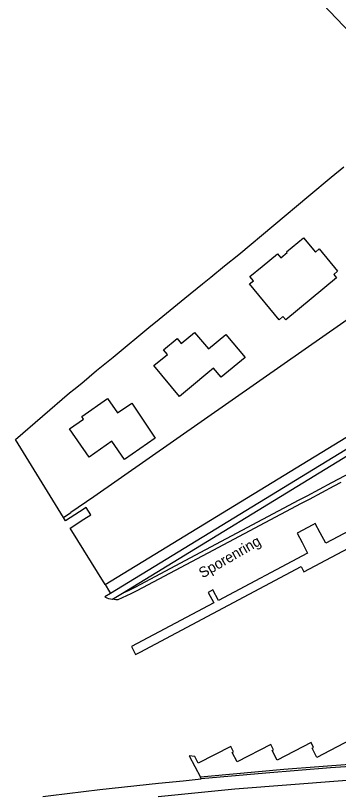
# Model space of a CAD drawing. Extents: x 132994 to 136000, y 393499 to 395512.
# Drawn here: x 133048.3 to 133125.3, y 393500 to 393686.2 of the extents above; entities that cross this region are included whole.
import ezdxf

# ---------------------------------------------------------------- set-up
doc = ezdxf.new("R2010")
doc.units = 0
doc.layers.add('gg-anno-openbare ruimte label', color=7, linetype='Continuous')
doc.layers.add('gx-grn-maaiveld', color=7, linetype='Continuous')

msp = doc.modelspace()

# ---------------------------------------------------------------- linework, layer by layer
at = {"layer": 'gx-grn-maaiveld'}
for p, q in [((133106.57, 393704.88), (133142.87, 393666.43)), ((133059.67, 393566.55), (133061.45, 393567.74)), ((133071.36, 393547), (133073.8, 393548.49)), ((133092.58, 393504.16), (133092.37, 393504.55))]:
    msp.add_line(p, q, dxfattribs=at)
for points in [[(133059.67, 393566.55), (133048.28, 393585.09), (133061.13, 393596.24), (133062.15, 393597.06), (133064.05, 393598.58), (133067.58, 393601.55), (133071.52, 393604.79), (133080.58, 393612.24), (133081.65, 393613.12), (133088.67, 393618.83), (133092.84, 393622.21), (133094.86, 393623.85), (133098.14, 393626.51), (133101.51, 393629.25), (133118.26, 393643.23), (133123.56, 393647.65), (133126.6, 393650.12)], [(133161.91, 393637.73), (133112.35, 393603.14), (133066.93, 393571.42), (133061.45, 393567.74)], [(133111.54, 393628.45), (133113.08, 393629.72), (133112.93, 393629.89), (133117, 393633.23), (133119.8, 393629.82), (133120.73, 393630.58), (133125.11, 393625.25), (133124.18, 393624.48), (133124.82, 393623.71), (133112.71, 393613.69), (133112.07, 393614.47), (133111.13, 393613.68), (133104.1, 393622.23), (133105.02, 393622.98), (133104.18, 393623.99), (133107.07, 393626.38), (133110.75, 393629.4), (133111.54, 393628.45)], [(133069.63, 393550.54), (133069.65, 393550.55), (133127.07, 393585.61), (133180.26, 393618.13)], [(133182, 393616.26), (133128.37, 393583.48), (133070.95, 393548.41)], [(133073.8, 393548.49), (133128.93, 393582.14), (133181.86, 393614.5), (133182.06, 393614.19)], [(133073.8, 393548.49), (133075.37, 393549.18), (133076.77, 393549.93), (133093.68, 393558.88), (133115.92, 393570.7), (133117.83, 393571.72), (133123.73, 393574.86), (133125.39, 393575.74), (133184.23, 393607.03), (133186.27, 393608.11), (133189.1, 393609.62), (133189.81, 393609.99), (133186.09, 393613.93)], [(133098.43, 393610.19), (133103.01, 393604.7), (133097.34, 393599.97), (133095.51, 393602.17), (133094.15, 393601.04), (133090.24, 393597.78), (133087.39, 393595.4), (133081.27, 393602.74), (133084.49, 393605.42), (133083.58, 393606.51), (133086.81, 393609.2), (133087.8, 393608.01), (133091, 393610.68), (133094.29, 393606.74), (133098.43, 393610.19)], [(133076.01, 393593.79), (133081.61, 393585.44), (133074.29, 393580.35), (133071.27, 393584.7), (133065.86, 393580.94), (133061.16, 393587.66), (133064.51, 393590), (133064.07, 393590.62), (133070.21, 393594.91), (133072.61, 393591.45), (133076.01, 393593.79)], [(133125.86, 393574.86), (133124.2, 393573.97), (133118.3, 393570.84), (133116.39, 393569.82), (133094.15, 393558), (133077.24, 393549.04), (133075.81, 393548.28), (133072.65, 393546.89), (133072.22, 393546.89), (133071.79, 393546.93), (133071.36, 393547)], [(133069.63, 393550.54), (133061.26, 393563.99), (133064.57, 393566.12), (133066.22, 393567.17), (133065.12, 393568.89), (133063.49, 393567.84), (133060.17, 393565.74), (133059.67, 393566.55)], [(133129.7, 393570.36), (133130.88, 393568.16), (133132.21, 393565.64), (133122.29, 393560.37), (133120.91, 393562.86), (133119.74, 393565.06), (133119.18, 393564.76), (133115.45, 393562.78), (133116.63, 393560.55), (133117.9, 393558.01), (133096.7, 393546.75), (133095.37, 393549.25), (133094.22, 393548.64), (133095.55, 393546.14), (133075.91, 393535.71), (133076.9, 393533.82), (133078.02, 393534.42), (133116.41, 393554.84), (133117.07, 393553.59), (133140.9, 393566.23)], [(133069.63, 393550.54), (133070.7, 393548.82), (133070.95, 393548.41)], [(133070.95, 393548.41), (133069.58, 393547.58), (133070.01, 393547.37), (133070.45, 393547.21), (133070.9, 393547.08), (133071.36, 393547)], [(133128.21, 393513.5), (133120.17, 393509.31), (133119.02, 393511.51), (133119.37, 393511.69), (133118.76, 393512.86), (133110.69, 393508.65), (133109.48, 393510.95), (133109.81, 393511.12), (133109.14, 393512.4), (133101.15, 393508.24), (133099.98, 393510.48), (133100.28, 393510.63), (133099.61, 393511.93), (133091.86, 393507.89), (133091.01, 393509.51), (133089.65, 393509.66), (133092.37, 393504.55)], [(133082.26, 393500), (133100.55, 393501.78), (133138.62, 393504.76), (133156.02, 393505.62), (133173.42, 393506.24), (133190.83, 393506.64), (133215.77, 393506.96), (133221.65, 393507.02), (133230.74, 393507.2), (133238.53, 393507.51), (133242.58, 393507.83), (133251.87, 393508.62), (133260.45, 393509.37), (133272.32, 393510.31), (133281.24, 393511.06), (133284.64, 393511.34)], [(133241.58, 393511.31), (133241.13, 393511.19), (133238.1, 393510.98), (133215.96, 393510.56), (133203.38, 393510.4), (133181.36, 393509.98), (133159.36, 393509.28), (133137.36, 393508.29), (133112.27, 393506.38), (133094.13, 393504.75), (133092.37, 393504.55)], [(133241.58, 393511.31), (133241.59, 393510.78), (133238.19, 393510.62), (133230.47, 393510.26), (133221.89, 393510.1), (133215.62, 393510.05), (133190.01, 393509.77), (133164.4, 393509.05), (133138.8, 393507.88), (133123.38, 393506.8), (133107.97, 393505.57), (133092.58, 393504.16)], [(133054.79, 393500), (133056.7, 393500.24), (133068.4, 393501.62), (133082.4, 393503.14), (133088.23, 393503.74), (133092.58, 393504.16)]]:
    msp.add_lwpolyline(points, dxfattribs=at)

# ---------------------------------------------------------------- texts
at = {"layer": 'gg-anno-openbare ruimte label'}
msp.add_text('Sporenring', height=2.5, rotation=30, dxfattribs=at).set_placement((133092.88, 393551.96))

doc.saveas('drawing.dxf')
